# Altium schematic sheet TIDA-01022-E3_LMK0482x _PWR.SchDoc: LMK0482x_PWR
size 431 x 279 mm; Date: Not shown in title block; ApprovedBy: Not shown in title block; CheckedBy: Not shown in title block; Author: Not shown in title block; CompanyName: Not shown in title block; DrawnBy: Avinash N; Engineer: Not shown in title block; Organization: Not shown in title block; Address1: Not shown in title block; Address2: Not shown in title block; Address3: Not shown in title block; Address4: Not shown in title block; DocumentNumber: 1; Revision: Use project parameter SCH_Rev; SheetNumber: 14; SheetTotal: 26; PageSetup: Record=PageOptions¦CenterHorizontal=True¦CenterVertical=True¦PrintScale=1.00¦XCorrection=1.00¦YCorrection=1.00¦PrintKind=0¦BorderSize=5000000¦LeftOffset=0¦BottomOffset=0¦Orientation=2¦PaperLength=1000¦PaperWidth=1000¦Scale=100¦PaperSource=15¦PrintQuality=600¦MediaType=1¦DitherType=10¦PaperKind=Letter¦PrintScaleMode=1
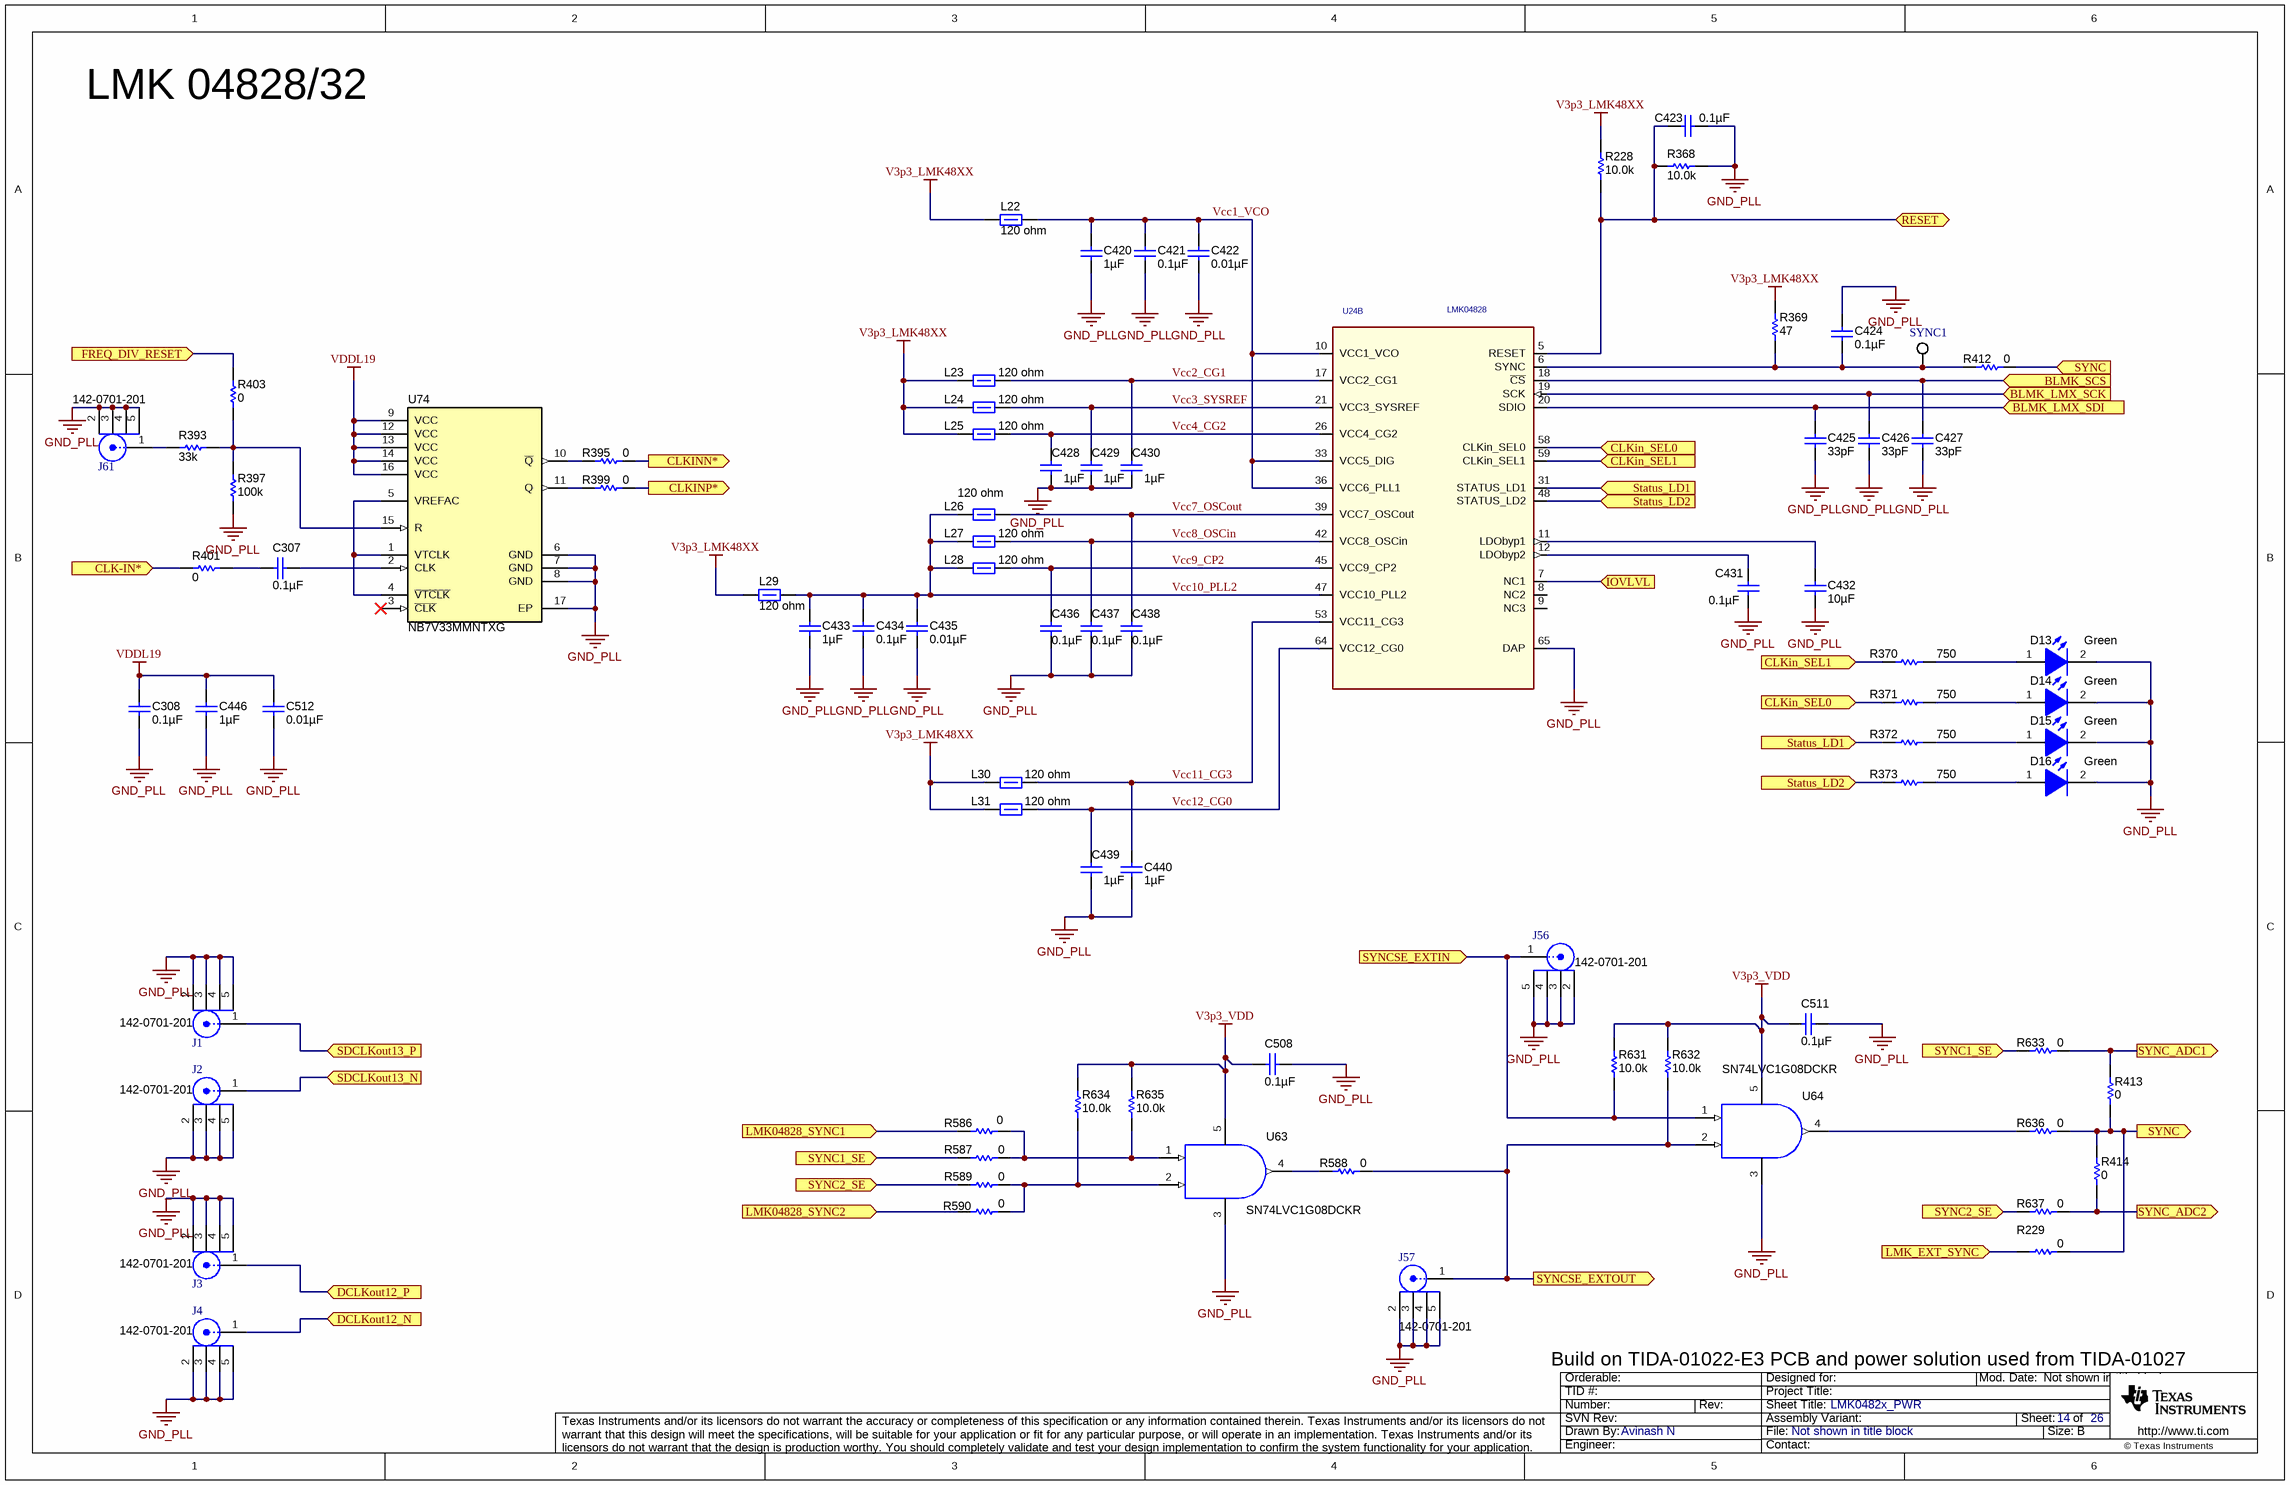
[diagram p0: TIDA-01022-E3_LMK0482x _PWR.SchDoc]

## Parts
C307  ValueDisplayed: 0.1µF  [0201_033]  (hidden comment: GRM033R60J104KE19D)
C308  ValueDisplayed: 0.1µF  [0402]  (hidden comment: C1005X7R1E104M050BB)
C420  ValueDisplayed: 1µF  [0402]  (hidden comment: C1005X7S1A105K050BC)
C421  ValueDisplayed: 0.1µF  [0402]  (hidden comment: GRM155R71C104KA88D)
C422  ValueDisplayed: 0.01µF  [0402]  (hidden comment: GRM155R71E103KA01D)
C423  ValueDisplayed: 0.1µF  [0402]  (hidden comment: C1005X7R1E104M050BB)
C424  ValueDisplayed: 0.1µF  [0402]  (hidden comment: C1005X7R1E104M050BB)
C425  ValueDisplayed: 33pF  [0603L]  (hidden comment: C0603C330J5GACTU)
C426  ValueDisplayed: 33pF  [0603L]  (hidden comment: C0603C330J5GACTU)
C427  ValueDisplayed: 33pF  [0603L]  (hidden comment: C0603C330J5GACTU)
C428  ValueDisplayed: 1µF  [0402]  (hidden comment: C1005X7S1A105K050BC)
C429  ValueDisplayed: 1µF  [0402]  (hidden comment: C1005X7S1A105K050BC)
C430  ValueDisplayed: 1µF  [0402]  (hidden comment: C1005X7S1A105K050BC)
C431  ValueDisplayed: 0.1µF  [0603]  (hidden comment: C0603C104J3RACTU)
C432  ValueDisplayed: 10µF  [0805_HV]  (hidden comment: C0805C106K8PACTU)
C433  ValueDisplayed: 1µF  [0402]  (hidden comment: C1005X7S1A105K050BC)
C434  ValueDisplayed: 0.1µF  [0402]  (hidden comment: GRM155R71C104KA88D)
C435  ValueDisplayed: 0.01µF  [0402]  (hidden comment: GRM155R71E103KA01D)
C436  ValueDisplayed: 0.1µF  [0402]  (hidden comment: C1005X7R1E104M050BB)
C437  ValueDisplayed: 0.1µF  [0402]  (hidden comment: C1005X7R1E104M050BB)
C438  ValueDisplayed: 0.1µF  [0402]  (hidden comment: C1005X7R1E104M050BB)
C439  ValueDisplayed: 1µF  [0402]  (hidden comment: C1005X7S1A105K050BC)
C440  ValueDisplayed: 1µF  [0402]  (hidden comment: C1005X7S1A105K050BC)
C446  ValueDisplayed: 1µF  [0402]  (hidden comment: C1005X7S1A105K050BC)
C508  ValueDisplayed: 0.1µF  [0402]  (hidden comment: GRM155R71C104KA88D)
C511  ValueDisplayed: 0.1µF  [0402]  (hidden comment: GRM155R71C104KA88D)
C512  ValueDisplayed: 0.01µF  [0402]  (hidden comment: GRM155R71E103KA01D)
D13  value Green  [LTST-C191_Green]  (hidden comment: LTST-C191TGKT)
D14  value Green  [LTST-C191_Green]  (hidden comment: LTST-C191TGKT)
D15  value Green  [LTST-C191_Green]  (hidden comment: LTST-C191TGKT)
D16  value Green  [LTST-C191_Green]  (hidden comment: LTST-C191TGKT)
J1  142-0701-201  [Johnson_142-0701-20x]
J2  142-0701-201  [Johnson_142-0701-20x]
J3  142-0701-201  [Johnson_142-0701-20x]
J4  142-0701-201  [Johnson_142-0701-20x]
J56  142-0701-201  [Johnson_142-0701-20x]
J57  142-0701-201  [Johnson_142-0701-20x]
J61  142-0701-201  [Johnson_142-0701-20x]
L22  ValueDisplayed: 120 ohm  [0603]  (hidden comment: BLM18AG121SN1D)
L23  ValueDisplayed: 120 ohm  [0603]  (hidden comment: BLM18AG121SN1D)
L24  ValueDisplayed: 120 ohm  [0603]  (hidden comment: BLM18AG121SN1D)
L25  ValueDisplayed: 120 ohm  [0603]  (hidden comment: BLM18AG121SN1D)
L26  ValueDisplayed: 120 ohm  [0603]  (hidden comment: BLM18AG121SN1D)
L27  ValueDisplayed: 120 ohm  [0603]  (hidden comment: BLM18AG121SN1D)
L28  ValueDisplayed: 120 ohm  [0603]  (hidden comment: BLM18AG121SN1D)
L29  ValueDisplayed: 120 ohm  [0603]  (hidden comment: BLM18AG121SN1D)
L30  ValueDisplayed: 120 ohm  [0603]  (hidden comment: BLM18AG121SN1D)
L31  ValueDisplayed: 120 ohm  [0603]  (hidden comment: BLM18AG121SN1D)
R228  ValueDisplayed: 10.0k  [0402]  (hidden comment: ERJ-2RKF1002X)
R229  ValueDisplayed: 0  [0402]  (hidden comment: CRCW04020000Z0ED)
R368  ValueDisplayed: 10.0k  [0402]  (hidden comment: ERJ-2RKF1002X)
R369  ValueDisplayed: 47  [0402]  (hidden comment: CRCW040247R0JNED)
R370  ValueDisplayed: 750  [0603]  (hidden comment: CRCW0603750RFKEA)
R371  ValueDisplayed: 750  [0603]  (hidden comment: CRCW0603750RFKEA)
R372  ValueDisplayed: 750  [0603]  (hidden comment: CRCW0603750RFKEA)
R373  ValueDisplayed: 750  [0603]  (hidden comment: CRCW0603750RFKEA)
R393  ValueDisplayed: 33k  [0402]  (hidden comment: CRCW040233K0JNED)
R395  ValueDisplayed: 0  [0201]  (hidden comment: ERJ-1GN0R00C)
R397  ValueDisplayed: 100k  [0402]  (hidden comment: CRCW0402100KFKED)
R399  ValueDisplayed: 0  [0201]  (hidden comment: ERJ-1GN0R00C)
R401  ValueDisplayed: 0  [0201_ADC]  (hidden comment: CRCW02010000Z0ED)
R403  ValueDisplayed: 0  [0603]  (hidden comment: CRCW06030000Z0EA)
R412  ValueDisplayed: 0  [0402]  (hidden comment: CRCW04020000Z0ED)
R413  ValueDisplayed: 0  [0402]  (hidden comment: CRCW04020000Z0ED)
R414  ValueDisplayed: 0  [0402]  (hidden comment: CRCW04020000Z0ED)
R586  ValueDisplayed: 0  [0402]  (hidden comment: CRCW04020000Z0ED)
R587  ValueDisplayed: 0  [0402]  (hidden comment: CRCW04020000Z0ED)
R588  ValueDisplayed: 0  [0402]  (hidden comment: CRCW04020000Z0ED)
R589  ValueDisplayed: 0  [0402]  (hidden comment: CRCW04020000Z0ED)
R590  ValueDisplayed: 0  [0402]  (hidden comment: CRCW04020000Z0ED)
R631  ValueDisplayed: 10.0k  [0603]  (hidden comment: RT0603DRE0710KL)
R632  ValueDisplayed: 10.0k  [0603]  (hidden comment: RT0603DRE0710KL)
R633  ValueDisplayed: 0  [0402]  (hidden comment: CRCW04020000Z0ED)
R634  ValueDisplayed: 10.0k  [0603]  (hidden comment: RT0603DRE0710KL)
R635  ValueDisplayed: 10.0k  [0603]  (hidden comment: RT0603DRE0710KL)
R636  ValueDisplayed: 0  [0402]  (hidden comment: CRCW04020000Z0ED)
R637  ValueDisplayed: 0  [0402]  (hidden comment: CRCW04020000Z0ED)
SYNC1  5002  [Keystone5002]  (value not drawn)
U24  LMK04828  [NKD0064A]  (part B of 2)
U63  SN74LVC1G08DCKR  [DCK0005A_N]
U64  SN74LVC1G08DCKR  [DCK0005A_N]
U74  NB7V33MMNTXG  [QFN16-3x3MM_0_5]

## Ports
BLMK_LMX_SCK (in), BLMK_LMX_SDI (in), BLMK_SCS (in), CLK-IN* (in), CLKin_SEL0 (in), CLKin_SEL1 (in), CLKINN* (out), CLKINP* (out), DCLKout12_N (in), DCLKout12_P (in), FREQ_DIV_RESET (in), IOVLVL (in), LMK04828_SYNC1 (in), LMK04828_SYNC2 (in), LMK_EXT_SYNC (in), RESET (bidir), SDCLKout13_N (in), SDCLKout13_P (in), Status_LD1 (in), Status_LD2 (in), SYNC1_SE (in), SYNC2_SE (in), SYNC (in), SYNC (out), SYNC_ADC1 (out), SYNC_ADC2 (out), SYNCSE_EXTIN (in), SYNCSE_EXTOUT (out)

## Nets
GND_PLL: C308.1 C420.2 C421.2 C422.2 C423.1 C424.1 C425.1 C426.1 C427.1 C428.2 C429.2 C430.2 C431.2 C432.2 C433.2 C434.2 C435.2 C436.1 C437.1 C438.1 C439.2 C440.2 C446.1 C508.2 C511.2 C512.1 D13.2(K) D14.2(K) D15.2(K) D16.2(K) J1.2 J1.3 J1.4 J1.5 J2.2 J2.3 J2.4 J2.5 J3.2 J3.3 J3.4 J3.5 J4.2 J4.3 J4.4 J4.5 J56.2 J56.3 J56.4 J56.5 J57.2 J57.3 J57.4 J57.5 J61.2 J61.3 J61.4 J61.5 R368.1 R397.1 U24.65(DAP) U63.3(V-) U64.3(V-) U74.6(GND) U74.7(GND) U74.8(GND) U74.17(EP)
V3p3_LMK48XX: L22.1 L23.1 L24.1 L25.1 L29.1 L30.1 L31.1 R228.1 R369.1
V3p3_VDD: C508.1 C511.1 R631.2 R632.2 R634.2 R635.2 U63.5(V+) U64.5(V+)
VDDL19: C308.2 C446.2 C512.2 U74.9(VCC) U74.12(VCC) U74.13(VCC) U74.14(VCC) U74.16(VCC)
BLMK_LMX_SCK: C426.2 U24.19(SCK) ; port BLMK_LMX_SCK
BLMK_LMX_SDI: C425.2 U24.20(SDIO) ; port BLMK_LMX_SDI
BLMK_SCS: C427.2 U24.18(~{CS}) ; port BLMK_SCS
CLK-IN*: R401.1 ; port CLK-IN*
CLKin_SEL0: R371.1 U24.58(CLKin_SEL0) ; port CLKin_SEL0
CLKin_SEL1: R370.1 U24.59(CLKin_SEL1) ; port CLKin_SEL1
CLKINN*: R395.1 ; port CLKINN*
CLKINP*: R399.1 ; port CLKINP*
DCLKout12_N: J4.1 ; port DCLKout12_N
DCLKout12_P: J3.1 ; port DCLKout12_P
FREQ_DIV_RESET: R403.2 ; port FREQ_DIV_RESET
IOVLVL: U24.7(NC1) ; port IOVLVL
LMK04828_SYNC1: R586.2 ; port LMK04828_SYNC1
LMK04828_SYNC2: R590.1 ; port LMK04828_SYNC2
LMK_EXT_SYNC: R229.1 ; port LMK_EXT_SYNC
RESET: C423.2 R228.2 R368.2 U24.5(RESET) ; port RESET
SDCLKout13_N: J2.1 ; port SDCLKout13_N
SDCLKout13_P: J1.1 ; port SDCLKout13_P
Status_LD1: R372.1 U24.31(STATUS_LD1) ; port Status_LD1
Status_LD2: R373.1 U24.48(STATUS_LD2) ; port Status_LD2
SYNC: R229.2 R412.2 R413.1 R414.2 R636.2 ; port SYNC
SYNC1_SE: R587.1 R633.1 ; port SYNC1_SE
SYNC2_SE: R589.1 R637.1 ; port SYNC2_SE
SYNC_ADC1: R413.2 R633.2 ; port SYNC_ADC1
SYNC_ADC2: R414.1 R637.2 ; port SYNC_ADC2
SYNCSE_EXTIN: J56.1 R631.1 U64.1(A) ; port SYNCSE_EXTIN
SYNCSE_EXTOUT: J57.1 R588.2 R632.1 U64.2(B) ; port SYNCSE_EXTOUT
Vcc1_VCO: C420.1 C421.1 C422.1 L22.2 U24.10(VCC1_VCO) U24.33(VCC5_DIG) U24.36(VCC6_PLL1)
Vcc2_CG1: C430.1 L23.2 U24.17(VCC2_CG1)
Vcc3_SYSREF: C429.1 L24.2 U24.21(VCC3_SYSREF)
Vcc4_CG2: C428.1 L25.2 U24.26(VCC4_CG2)
Vcc7_OSCout: C438.2 L26.2 U24.39(VCC7_OSCout)
Vcc8_OSCin: C437.2 L27.2 U24.42(VCC8_OSCin)
Vcc9_CP2: C436.2 L28.2 U24.45(VCC9_CP2)
Vcc10_PLL2: C433.1 C434.1 C435.1 L26.1 L27.1 L28.1 L29.2 U24.47(VCC10_PLL2)
Vcc11_CG3: C440.1 L30.2 U24.53(VCC11_CG3)
Vcc12_CG0: C439.1 L31.2 U24.64(VCC12_CG0)
NetC307_1: C307.1 R401.2
NetC307_2: C307.2 U74.2(CLK)
NetC424_2: C424.2 R369.2 R412.1 SYNC1.1 U24.6(SYNC)
NetC431_1: C431.1 U24.12(LDObyp2)
NetC432_1: C432.1 U24.11(LDObyp1)
NetD13_1: D13.1(A) R370.2
NetD14_1: D14.1(A) R371.2
NetD15_1: D15.1(A) R372.2
NetD16_1: D16.1(A) R373.2
NetJ61_1: J61.1 R393.1
NetR393_2: R393.2 R397.2 R403.1 U74.15(R)
NetR395_2: R395.2 U74.10(~{Q})
NetR399_2: R399.2 U74.11(Q)
NetR586_1: R586.1 R587.2 R635.1 U63.1(A)
NetR588_1: R588.1 U63.4(Y)
NetR589_2: R589.2 R590.2 R634.1 U63.2(B)
NetR636_1: R636.1 U64.4(Y)
NetU74_1: U74.1(VTCLK) U74.4(~{VTCLK}) U74.5(VREFAC)

Not connected (* = marked no-connect by the designer): U24 8(NC2) 9(NC3); U74 3(~{CLK})*

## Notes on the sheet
- LMK 04828/32
- Build on TIDA-01022-E3 PCB and power solution used from TIDA-01027

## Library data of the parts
C307 = GRM033R60J104KE19D: CAP, CERM, 0.1 µF, 6.3 V,+/- 10%, X5R, 0201; Manufacturer: MuRata; Cap_Case: 0201; Polarized: N; TaMax_C: 85; TaMin_C: -55; Tolerance_%: 10; VDC_V: 6.3; Cap_F: 0.0000001; CompType: Capacitor; Value: 0.1uF; Value2: 6.3V; U/M: EA; SizeArea_mm2: 0.18; SizeAreaWB_mm2: 2.08; SizeX_mm: 0.6; SizeY_mm: 0.3; SizeZ_mm: 0.33; AEC Category: Q200; Green_Lifecycle: Active; Green_REACh: Passed
C308 = C1005X7R1E104M050BB: CAP, CERM, 0.1 µF, 25 V,+/- 20%, X7R, 0402; Manufacturer: TDK; Polarized: N; TaMax_C: 125; TaMin_C: -55; Tolerance_%: 20; VDC_V: 25; Cap_F: 0.0000001; CompType: Capacitor; Value: 0.1uF; Value2: 25V; U/M: EA; SizeArea_mm2: 0.5; SizeAreaWB_mm2: 3; SizeX_mm: 1; SizeZ_mm: 0.6; AEC Category: Q200; Green_Lifecycle: NRND; Green_REACh: Passed
C420 C428-C430 C433 C439 C440 = C1005X7S1A105K050BC: CAP, CERM, 1 µF, 10 V, +/- 10%, X7S, 0402; Manufacturer: TDK; Polarized: N; CompType: Capacitor; Value: 1uF; U/M: EA; Cap_F: 0.000001; Tolerance_%: 10; ESR_ohm: 0.011416; Value1: 0.011416 ohm; Value2: 10V; IRMS_A: 1.483; TaMin_C: -55; TaMax_C: 125; SizeArea_mm2: 0.5; SizeAreaWB_mm2: 3; SizeX_mm: 1; SizeZ_mm: 0.6; AEC Category: Q200
C421 C434 C508 C511 = GRM155R71C104KA88D: CAP, CERM, 0.1 µF, 16 V, +/- 10%, X7R, 0402; Manufacturer: MuRata; Polarized: N; CompType: Capacitor; Value: 0.1uF; U/M: EA; Cap_F: 0.0000001; Tolerance_%: 10; Value1: Unknown; VDC_V: 16; Value2: 16V; TaMin_C: -55; TaMax_C: 125; SizeArea_mm2: 0.5; SizeAreaWB_mm2: 3; SizeX_mm: 1; SizeZ_mm: 0.6; AEC Category: Q200
C422 C435 = GRM155R71E103KA01D: CAP, CERM, 0.01 µF, 25 V, +/- 10%, X7R, 0402; Manufacturer: MuRata; Polarized: N; CompType: Capacitor; Value: 0.01uF; U/M: EA; Cap_F: 0.00000001; Tolerance_%: 10; Value1: Unknown; VDC_V: 25; Value2: 25V; TaMin_C: -55; TaMax_C: 125; SizeArea_mm2: 0.5; SizeAreaWB_mm2: 3; SizeX_mm: 1; SizeZ_mm: 0.6; AEC Category: Q200
C423 C424 C436-C438 = C1005X7R1E104M050BB: CAP, CERM, 0.1 µF, 25 V, +/- 20%, X7R, 0402; Manufacturer: TDK; Polarized: N; TaMax_C: 125; TaMin_C: -55; Tolerance_%: 20; VDC_V: 25; Cap_F: 0.0000001; CompType: Capacitor; Value: 0.1uF; Value1: Unknown; Value2: 25V; U/M: EA; SizeArea_mm2: 0.5; SizeAreaWB_mm2: 3; SizeX_mm: 1; SizeZ_mm: 0.6; AEC Category: Q200
C425-C427 = C0603C330J5GACTU: CAP, CERM, 33pF, 50V, +/-5%, C0G/NP0, 0603; Manufacturer: Kemet; Cap_Case: 0603; Polarized: N; TaMax_C: 125; TaMin_C: -55; Tolerance_%: 5; VDC_V: 50; Cap_F: 0.000000000033; CompType: Capacitor; U/M: EA; Value1: Unknown
C431 = C0603C104J3RACTU: CAP, CERM, 0.1uF, 25V, +/-5%, X7R, 0603; Manufacturer: Kemet; Polarized: N; TaMax_C: 125; TaMin_C: -55; Tolerance_%: 5; VDC_V: 25; Cap_F: 0.0000001; CompType: Capacitor; Value1: Unknown; U/M: EA
C432 = C0805C106K8PACTU: CAP, CERM, 10uF, 10V, +/-10%, X5R, 0805; Manufacturer: Kemet; Cap_Case: 0805; ESR_Ohm: 0.003; IRMS_A: 11.43; Polarized: N; TaMax_C: 85; TaMin_C: -55; Tolerance_%: 10; Cap_F: 0.00001; CompType: Capacitor; Value1: 0.003 ohm; U/M: EA
C446 = C1005X7S1A105K050BC: CAP, CERM, 1 µF, 10 V,+/- 10%, X7S, 0402; Manufacturer: TDK; ESR_ohm: 0.011416; IRMS_A: 1.483; Polarized: N; TaMax_C: 125; TaMin_C: -55; Tolerance_%: 10; Cap_F: 0.000001; CompType: Capacitor; Value: 1uF; Value1: 0.011416 ohm; Value2: 10V; U/M: EA; SizeArea_mm2: 0.5; SizeAreaWB_mm2: 3; SizeX_mm: 1; SizeZ_mm: 0.6; AEC Category: Q200; Green_Lifecycle: Active; Green_REACh: Passed
C512 = GRM155R71E103KA01D: CAP, CERM, 0.01 µF, 25 V,+/- 10%, X7R, 0402; Manufacturer: MuRata; Polarized: N; TaMax_C: 125; TaMin_C: -55; Tolerance_%: 10; VDC_V: 25; Cap_F: 0.00000001; CompType: Capacitor; Value: 0.01uF; Value2: 25V; U/M: EA; SizeArea_mm2: 0.5; SizeAreaWB_mm2: 3; SizeX_mm: 1; SizeZ_mm: 0.6; AEC Category: Q200; Green_Lifecycle: Active; Green_REACh: Passed
D13-D16 = LTST-C191TGKT: LED, Green, SMD; Manufacturer: Lite-On; Type: InGaN; Vf_V: 3.2; Value2: 3.2V; Io_A: 0.02; Value1: W; U/M: EA
J1-J4 J56 J57 J61 = 142-0701-201: Connector, TH, SMA; Manufacturer: Emerson Network Power; SymbolCreator: X0208326
L22-L31 = BLM18AG121SN1D: Ferrite Bead, 120 ohm @ 100 MHz, 0.5 A, 0603; Manufacturer: MuRata; Value: 120 ohm; Imax_A: 0.5; DCR_ohm: 0.18; Value1: 0.18 ohm; Value2: 0.5A; SizeAreaWB_mm2: 4.68; SizeArea_mm2: 1.28; SizeX_mm: 1.6; SizeY_mm: 0.8; SizeZ_mm: 1; ZTyp@100MHz_Ohm: 120
R228 R368 = ERJ-2RKF1002X: RES, 10.0 k, 1%, 0.1 W, 0402; Manufacturer: Panasonic; CompType: Resistor; Value: 10.0k; Res_ohm: 10000; Value_Code: 10k0; Tolerance_%: 1; Power_W: 0.1; Value2: 0.1W; VDC_V: 50; TempCo: 100 ppm/C; SizeArea_mm2: 0.5; SizeZ_mm: 0.6; EIA_Code: E96; U/M: EA; AEC Category: Q200
R229 R412-R414 R586-R590 R633 R636 R637 = CRCW04020000Z0ED: RES, 0, 5%, 0.063 W, 0402; Manufacturer: Vishay-Dale; CompType: Resistor; Value: 0; Value_Code: 0000; Tolerance_%: 5; Power_W: 0.063; Value2: 0.063W; VDC_V: 50; TempCo: 200 ppm/C; SizeArea_mm2: 0.5; SizeX_mm: 1; SizeZ_mm: 0.6; EIA_Code: E24; U/M: EA; AEC Category: Q200
R369 = CRCW040247R0JNED: RES, 47, 5%, 0.063 W, 0402; Manufacturer: Vishay-Dale; CompType: Resistor; Value: 47; Value_Code: 47R0; Tolerance_%: 5; Power_W: 0.063; Value2: 0.063W; VDC_V: 50; TempCo: 200 ppm/C; SizeArea_mm2: 0.5; SizeX_mm: 1; SizeZ_mm: 0.6; EIA_Code: E24; U/M: EA; AEC Category: Q200
R370-R373 = CRCW0603750RFKEA: RES, 750, 1%, 0.1 W, 0603; Manufacturer: Vishay-Dale; CompType: Resistor; Value: 750; Value_Code: 750R; Tolerance_%: 1; Power_W: 0.1; Value2: 0.1W; VDC_V: 75; TempCo: 100 ppm/C; SizeArea_mm2: 1.28; SizeX_mm: 1.6; SizeY_mm: 0.8; EIA_Code: E96; U/M: EA; AEC Category: Q200
R393 = CRCW040233K0JNED: RES, 33 k, 5%, 0.063 W, 0402; Manufacturer: Vishay-Dale; CompType: Resistor; Value: 33k; Res_ohm: 33000; Value_Code: 33k0; Tolerance_%: 5; Power_W: 0.063; Value2: 0.063W; VDC_V: 50; TempCo: 200 ppm/C; SizeArea_mm2: 0.5; SizeX_mm: 1; SizeZ_mm: 0.6; EIA_Code: E24; U/M: EA; AEC Category: Q200; Green_Lifecycle: Active; Green_REACh: Passed
R395 R399 = ERJ-1GN0R00C: RES, 0, 5%, 0.05 W, AEC-Q200 Grade 0, 0201; Manufacturer: Panasonic; CompType: Resistor; Tolerance_%: 5; Power_W: 0.05; Value: 0; U/M: EA; Value_Code: 0000; Value2: 0.05W; EIA_Code: E24; TempCo: ppm/C; SizeArea_mm2: 0.18; SizeX_mm: 0.6; SizeY_mm: 0.3; SizeZ_mm: 0.26; AEC Category: Q200; AEC Qualified: Y
R397 = CRCW0402100KFKED: RES, 100 k, 1%, 0.063 W, 0402; Manufacturer: Vishay-Dale; CompType: Resistor; Value: 100k; Res_ohm: 100000; Tolerance_%: 1; Power_W: 0.063; Value2: 0.063W; VDC_V: 50; TempCo: 100 ppm/C; SizeArea_mm2: 0.5; SizeZ_mm: 0.6; EIA_Code: E96; U/M: EA; AEC Category: Q200; Green_Lifecycle: Active; Green_REACh: Passed
R401 = CRCW02010000Z0ED: RES, 0, 5%, 0.05 W, 0201; Manufacturer: Vishay-Dale; CompType: Resistor; Tolerance_%: 5; Power_W: 0.05; Value: 0; U/M: EA; Value_Code: 0000; Value2: 0.05W; EIA_Code: E24; TempCo: ppm/C; SizeArea_mm2: 0.18; SizeX_mm: 0.6; SizeY_mm: 0.3; SizeZ_mm: 0.26; AEC Category: Q200; AEC Qualified: N
R403 = CRCW06030000Z0EA: RES, 0, 5%, 0.1 W, 0603; Manufacturer: Vishay-Dale; CompType: Resistor; Tolerance_%: 5; VDC_V: 75; Power_W: 0.1; Value: 0; U/M: EA; Value_Code: 0000; Value2: 0.1W; EIA_Code: E24; TempCo: 200 ppm/C; SizeArea_mm2: 1.28; SizeX_mm: 1.6; SizeY_mm: 0.8; SizeZ_mm: 1; AEC Category: Q200; Green_Lifecycle: Active; Green_REACh: Passed
R631 R632 R634 R635 = RT0603DRE0710KL: RES, 10.0 k, 0.5%, 0.1 W, 0603; Manufacturer: Yageo America; CompType: Resistor; Value: 10.0k; Res_ohm: 10000; Value_Code: 10k0; Tolerance_%: 0.5; Power_W: 0.1; Value2: 0.1W; VDC_V: 75; TempCo: 50 ppm/C; SizeArea_mm2: 1.28; SizeX_mm: 1.6; SizeY_mm: 0.8; SizeZ_mm: 1; EIA_Code: E192; U/M: EA; AEC Category: Q200
SYNC1 = 5002: Test Point, Miniature, White, TH; Manufacturer: Keystone; CompType: Test Point Loop; ContactFinish: Silver; Green_Lifecycle: Active; Green_REACh: Passed
U24 = LMK04828: LMK04828BISQE/NOPB; Manufacturer: Texas Instruments
U63 U64 = SN74LVC1G08DCKR: Single 2-Input Positive-AND Gate, DCK0005A (SOT-5); Alternate PartNumber: SN74LVC1G08DCKT; Manufacturer: Texas Instruments; CompType: IC; SizeArea_mm2: 4.2; SizeAreaWB_mm2: 9.3; SizeX_mm: 2.1; SizeY_mm: 2; SizeZ_mm: 1.1; U/M: EA
U74 = NB7V32M: 1.8V / 2.5V, 10GHz ÷4 Clock Divider with CML Outputs, QFN-16; Manufacturer: ON Semiconductor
